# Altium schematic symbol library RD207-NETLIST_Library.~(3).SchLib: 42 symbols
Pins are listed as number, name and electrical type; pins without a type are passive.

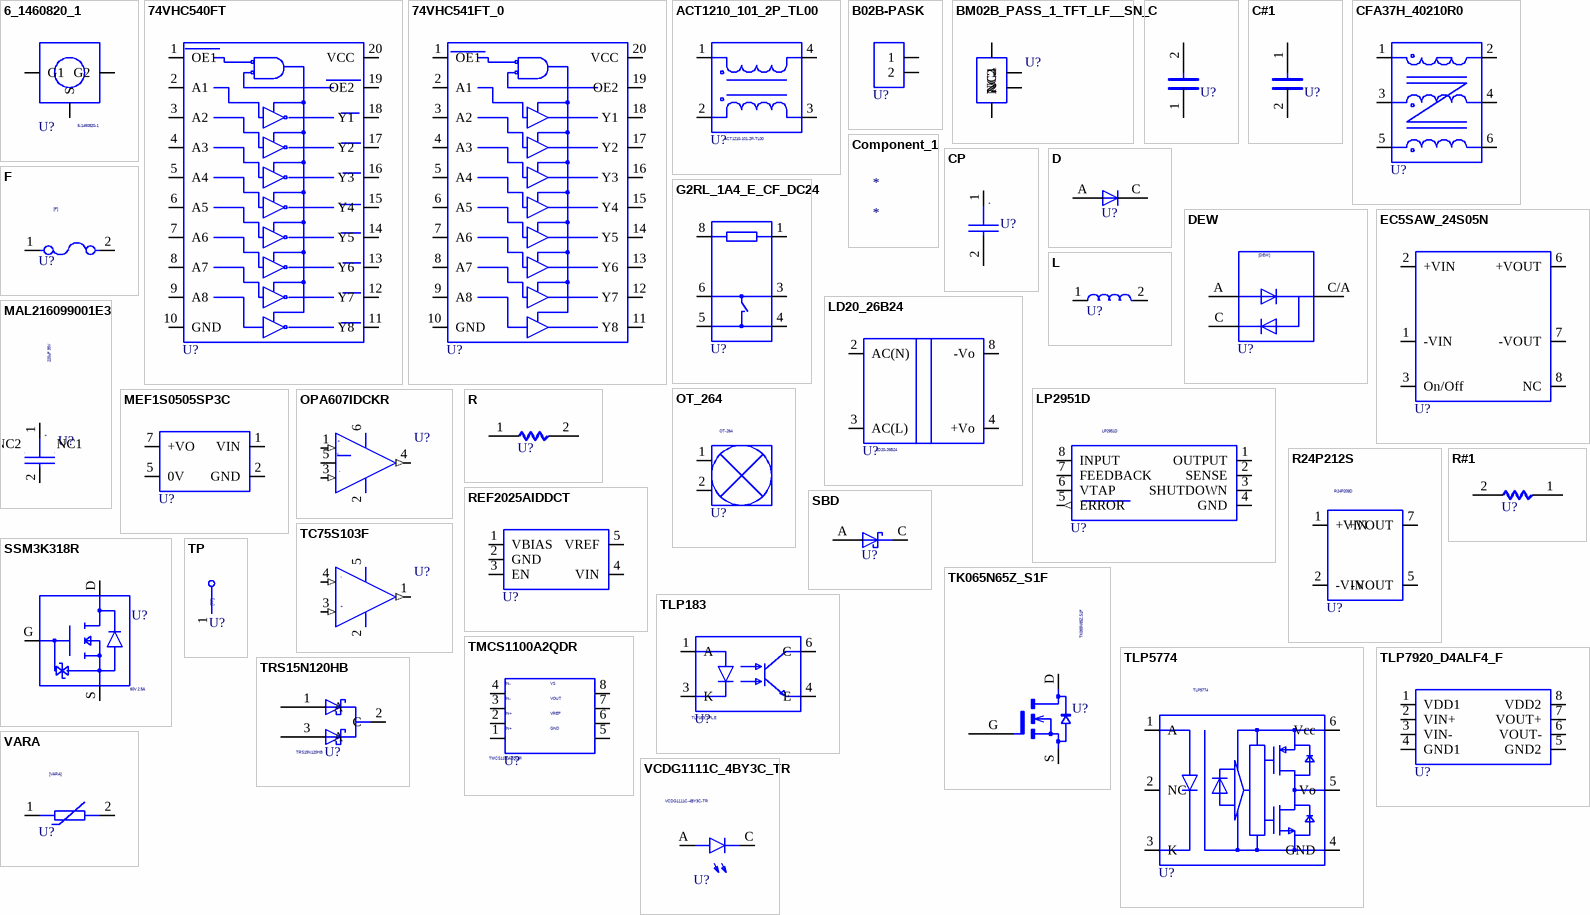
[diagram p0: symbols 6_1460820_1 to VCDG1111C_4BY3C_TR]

## 6_1460820_1
designator U?, comment 6-1460820-1
MMCX Connector, 170V; MANUFACTURER: TE Connectivity; TIME: 11:39:41; UPDATEUSER: t5459927; UPDATETIME: 13:55:13; SAVECOUNT: 2; SAVEAREA0: -9060,-19760,18940,737; OriginalSymbolOrigin: (0,0); Altium-Right: 40
pins: G1, G2, S

## 74VHC540FT
designator U?  (value not drawn)
Buffer; MANUFACTURER: TOSHIBA; TIME: 16:53:55; UPDATEUSER: t5459927; UPDATETIME: 14:02:13; SAVECOUNT: 3; SAVEAREA0: -17145,-25086,46711,10262; OriginalSymbolOrigin: (0,0); Altium-Right: 120; Altium-Bottom: 200
pins: 1 OE1, 2 A1, 3 A2, 4 A3, 5 A4, 6 A5, 7 A6, 8 A7, 9 A8, 10 GND, 11 Y8, 12 Y7, 13 Y6, 14 Y5, 15 Y4, 16 Y3, 17 Y2, 18 Y1, 19 OE2, 20 VCC

## 74VHC541FT_0
designator U?, comment 74VHC541FT  (value not drawn)
Buffer; MANUFACTURER: TOSHIBA; COMP: 74VHC541FT_0; TIME: 16:53:58; UPDATEUSER: t5459927; UPDATETIME: 13:53:55; SAVECOUNT: 7; SAVEAREA0: -71383,-60147,106563,38358; OriginalSymbolOrigin: (0,0); Altium-Right: 120; Altium-Bottom: 200
pins: 1 OE1, 2 A1, 3 A2, 4 A3, 5 A4, 6 A5, 7 A6, 8 A7, 9 A8, 10 GND, 11 Y8, 12 Y7, 13 Y6, 14 Y5, 15 Y4, 16 Y3, 17 Y2, 18 Y1, 19 OE2, 20 VCC

## ACT1210_101_2P_TL00
designator U?, comment ACT1210-101-2P-TL00
150mA; MAKER: TDK; NOTE: 100uH; TIME: 11:39:41; UPDATEUSER: t5459927; UPDATETIME: 16:14:20; SAVECOUNT: 2; SAVEAREA0: -3836,-15544,18561,852; OriginalSymbolOrigin: (0,0); Altium-Right: 60
pins: 1, 2, 3, 4

## B02B-PASK
designator U?, comment BM02B-PASS-1-TFT(LF)(SN)  (value not drawn)
Connector, 250V, 3A; MANUFACTURER: JST; COMP: B02B-PASK; NOTE: 2pin; TIME: 11:39:42; UPDATEUSER: t5459927; UPDATETIME: 16:50:18; SAVECOUNT: 6; SAVEAREA0: -5711,-10440,12954,3224; OriginalSymbolOrigin: (0,0); Altium-Right: 20; Altium-Bottom: 30
pins: 1, 2

## BM02B_PASS_1_TFT_LF__SN_
designator U?, comment BM02B-PASS-1-TFT(LF)(SN)  (value not drawn)
Connector, 250V, 3A; MANUFACTURER: JST; NOTE: 2pin; TIME: 11:39:42; UPDATEUSER: t5459927; UPDATETIME: 16:51:32; SAVECOUNT: 4; SAVEAREA0: -29189,-27933,36825,20394; OriginalSymbolOrigin: (0,0); Altium-Right: 20; Altium-Bottom: 30
pins: 1, 2, NC1, NC2

## C
designator U?  (value not drawn)
OriginalSymbolOrigin: (2540,7620); Altium-Right: 20; Altium-Bottom: 10
pins: 1, 2

## C#1
designator U?, comment C  (value not drawn)
OriginalSymbolOrigin: (2540,7620); Altium-Right: 20; Altium-Bottom: 10
pins: 1 2, 2 1

## CFA37H_40210R0
designator U?, comment CFA37H-40210R0  (value not drawn)
3phase Common Mode Choke; MAKER: Tamura; NOTE: 3phase, 4mH@100kHz, 10A; TIME: 11:39:42; UPDATEUSER: t5459927; UPDATETIME: 15:32:41; SAVECOUNT: 2; SAVEAREA0: -28588,-28970,43380,3822; OriginalSymbolOrigin: (0,0); Altium-Right: 60; Altium-Bottom: 80
pins: 1, 2, 3, 4, 5, 6

## Component_1
designator *

## CP
designator U?  (value not drawn)
SAVEAREA0: -1450,-153,20294,13055; SAVECOUNT: 52; TIME: 15:02:55; UPDATEUSER: fukuda-y; UPDATETIME: 16:13:42; OriginalSymbolOrigin: (2540,10160); Altium-Right: 20
pins: 1 2, 2 1

## D
designator U?  (value not drawn)
SAVEAREA0: -225,-91,12804,7836; SAVECOUNT: 3; TIME: 14:49:55; UPDATEUSER: 19870035; UPDATETIME: 14:20:16; OriginalSymbolOrigin: (5080,5080); Altium-Right: 10; Altium-Bottom: 20
pins: A, C

## DEW
designator U?  (value not drawn)
SAVEAREA0: -10024,-234,32508,20938; TIME: 14:49:55; UPDATEUSER: 19990028; UPDATETIME: 14:00:58; SAVECOUNT: 4; OriginalSymbolOrigin: (5080,17780); Altium-Right: 50; Altium-Bottom: 60
pins: A, C, C/A AC

## EC5SAW_24S05N
designator U?, comment EC5SAW-24S05N  (value not drawn)
DC/DC Converter; MANUFACTURER: CINCON; TIME: 11:39:40; UPDATEUSER: t5459927; UPDATETIME: 14:27:04; SAVECOUNT: 4; SAVEAREA0: -8840,-26929,31144,2341; OriginalSymbolOrigin: (0,0); Altium-Right: 90; Altium-Bottom: 100
pins: 1 -VIN, 2 +VIN, 3 On/Off, 6 +VOUT, 7 -VOUT, 8 NC

## F
designator U?  (value not drawn)
OriginalSymbolOrigin: (2540,5080); Altium-Right: 40; Altium-Bottom: 20
pins: 1, 2

## G2RL_1A4_E_CF_DC24
designator U?, comment G2RL-1A4-E-CF DC24  (value not drawn)
Power Relay; MANUFACTURER: OMRON; NOTE: 16A AC250V; TIME: 11:39:42; UPDATEUSER: t5459927; UPDATETIME: 16:09:17; SAVECOUNT: 4; SAVEAREA0: -30398,-23390,50563,13500; OriginalSymbolOrigin: (5080,7620); Altium-Right: 40; Altium-Bottom: 80
pins: 1, 3, 4, 5, 6, 8

## L
designator U?  (value not drawn)
OriginalSymbolOrigin: (2540,5080); Altium-Right: 30; Altium-Bottom: 20
pins: 1, 2

## LD20_26B24
designator U?, comment LD20-26B24
AC/DC Converter; MANUFACTURER: Mornsun; TIME: 11:39:42; UPDATEUSER: t5459927; UPDATETIME: 17:04:57; SAVECOUNT: 2; SAVEAREA0: -3533,-18371,23278,1256; OriginalSymbolOrigin: (0,0); Altium-Right: 80; Altium-Bottom: 70
pins: 2 AC(N), 3 AC(L), 4 +Vo, 8 -Vo

## LP2951D
designator U?
Voltage Regulators; MANUFACTURER: Txsas Instruments; TIME: 16:53:55; UPDATEUSER: t5459927; UPDATETIME: 16:15:29; SAVECOUNT: 3; SAVEAREA0: -15946,-25147,36340,13186; OriginalSymbolOrigin: (0,0); Altium-Right: 110; Altium-Bottom: 50
pins: 1 OUTPUT, 2 SENSE, 3 SHUTDOWN, 4 GND, 5 ERROR (out), 6 VTAP, 7 FEEDBACK, 8 INPUT

## MAL216099001E3
designator U?  NOTE: 220uF 35V  (hidden comment: MAL216099001E3)
Aluminum,35V,±20%; MANUFACTURER: Vishay; TIME: 11:39:41; UPDATEUSER: t5459927; UPDATETIME: 17:02:27; SAVECOUNT: 2; SAVEAREA0: -15593,-10586,20389,5809; OriginalSymbolOrigin: (0,0); Altium-Right: 20
pins: 1, 2, NC1, NC2

## MEF1S0505SP3C
designator U?  (value not drawn)
DC/DC Converter; MANUFACTURER: MORNSUN; TIME: 16:53:55; UPDATEUSER: t5459927; UPDATETIME: 13:45:31; SAVECOUNT: 4; SAVEAREA0: -2499,-12525,17820,2350; OriginalSymbolOrigin: (0,0); Altium-Right: 60; Altium-Bottom: 40
pins: 1 VIN, 2 GND, 5 0V, 7 +VO

## OPA607IDCKR
designator U?  (value not drawn)
TIME: 16:31:59; UPDATEUSER: t5459927; UPDATETIME: 14:13:01; SAVECOUNT: 17; SAVEAREA0: -9767,-7670,25158,17897; OriginalSymbolOrigin: (2540,10160); Altium-Right: 40
pins: 1 (in), 2 (in), 3 (in), 4 (out), 5 (io), 6 (in)

## OT_264
designator U?, comment OT-264
Terminal, 50A, M4; MANUFACTURER: Osada; TIME: 11:39:39; UPDATEUSER: t5459927; UPDATETIME: 13:18:21; SAVECOUNT: 2; SAVEAREA0: -3825,-10384,11105,546; OriginalSymbolOrigin: (0,0); Altium-Right: 40
pins: 1, 2

## R
designator U?  (value not drawn)
OriginalSymbolOrigin: (5080,5080); Altium-Right: 20
pins: 1, 2

## R24P212S
designator U?, comment R24P209D
DC/DC Converter; MANUFACTURER: RECOM; COMP: R24P212S; TIME: 16:53:55; UPDATEUSER: t5459927; UPDATETIME: 16:30:09; SAVECOUNT: 6; SAVEAREA0: -9940,-15240,22833,0; OriginalSymbolOrigin: (0,0); Altium-Right: 50; Altium-Bottom: 60
pins: 1 +VIN, 2 -VIN, 5 -VOUT, 7 +VOUT

## R#1
designator U?, comment R  (value not drawn)
OriginalSymbolOrigin: (5080,5080); Altium-Right: 20
pins: 1 2, 2 1

## REF2025AIDDCT
designator U?  (value not drawn)
Voltage References; MANUFACTURER: Texas Instruments; TIME: 11:39:41; UPDATEUSER: t5459927; UPDATETIME: 14:37:37; SAVECOUNT: 2; SAVEAREA0: -19574,-17685,36869,8033; OriginalSymbolOrigin: (0,0); Altium-Right: 70; Altium-Bottom: 40
pins: 1 VBIAS, 2 GND, 3 EN, 4 VIN, 5 VREF

## SBD
designator U?  (value not drawn)
SAVEAREA0: -4630,-153,17114,13055; TIME: 14:49:55; UPDATEUSER: fukuda-y; UPDATETIME: 08:16:22; SAVECOUNT: 9; OriginalSymbolOrigin: (5080,5080); Altium-Right: 20
pins: A, C

## SSM3K318R
designator U?  NOTE: 60V 2.5A  (hidden comment: SSM3K318R)
MOSFET; MANUFACTURER: TOSHIBA; TIME: 11:39:41; UPDATEUSER: t5459927; UPDATETIME: 14:45:44; SAVECOUNT: 2; SAVEAREA0: -8920,-18190,20944,3672; OriginalSymbolOrigin: (0,0); Altium-Right: 60
pins: D, G, S

## TC75S103F
designator U?  (value not drawn)
COMP: OPA4325IPWR_4; TIME: 16:31:59; UPDATEUSER: t5459927; UPDATETIME: 13:42:20; SAVECOUNT: 13; SAVEAREA0: 0,-513,15240,10643; OriginalSymbolOrigin: (2540,10160); Altium-Right: 40
pins: 1 (out), 2 (in), 3 (in), 4 (in), 5 (in)

## TK065N65Z_S1F
designator U?, comment TK065N65Z,S1F
Power MOS FET; MANUFACTURER: TOSHIBA; NOTE: 650V 30A; TIME: 11:39:42; UPDATEUSER: t5459927; UPDATETIME: 13:16:21; SAVECOUNT: 2; SAVEAREA0: -16850,-13021,18411,3375; OriginalSymbolOrigin: (0,0); Altium-Right: 40
pins: D, G, S

## TLP183
designator U?, comment TLP183(TPL,E
Photocoupler; MANUFACTURER: TOSHIBA; TIME: 11:39:41; UPDATEUSER: t5459927; UPDATETIME: 14:44:44; SAVECOUNT: 2; SAVEAREA0: -18362,-25993,35930,13752; OriginalSymbolOrigin: (0,0); Altium-Right: 70; Altium-Bottom: 50
pins: 1 A, 3 K, 4 E, 6 C

## TLP5774
designator U?
Photocouplers; MAKER: TOSHIBA; NOTE: 5kV 8mm; TIME: 11:39:41; UPDATEUSER: t5459927; UPDATETIME: 14:14:00; SAVECOUNT: 2; SAVEAREA0: -5083,-25908,32249,1421; OriginalSymbolOrigin: (0,0); Altium-Right: 110; Altium-Bottom: 100
pins: 1 A, 2 NC, 3 K, 4 GND, 5 Vo, 6 Vcc

## TLP7920_D4ALF4_F
designator U?, comment TLP7920(D4ALF1,F  (value not drawn)
Photocoupler; MANUFACTURER: TOSHIBA; COMP: TLP7920(D4ALF1,F_0; TIME: 16:53:58; UPDATEUSER: t5459927; UPDATETIME: 15:20:44; SAVECOUNT: 3; SAVEAREA0: -6054,-17255,23482,4367; OriginalSymbolOrigin: (0,0); Altium-Right: 90; Altium-Bottom: 50
pins: 1 VDD1, 2 VIN+, 3 VIN-, 4 GND1, 5 GND2, 6 VOUT-, 7 VOUT+, 8 VDD2

## TMCS1100A2QDR
designator U?
TIME: 11:39:42; UPDATEUSER: t5459927; UPDATETIME: 14:02:58; SAVECOUNT: 5; SAVEAREA0: -9737,-18768,24721,6457; OriginalSymbolOrigin: (0,0); Altium-Right: 60; Altium-Bottom: 50
pins: 1, 2, 3, 4, 5, 6, 7, 8

## TP
designator U?  (value not drawn)
TIME: 16:12:21; UPDATEUSER: fukuda-y; UPDATETIME: 16:18:11; SAVECOUNT: 2; SAVEAREA0: -242,-92,12810,7836; OriginalSymbolOrigin: (0,7620); Altium-Right: 20; Altium-Bottom: 30
pins: 1

## TRS15N120HB
designator U?
SiC Schottky Barrier Diode Array; MANUFACTURER: TOSHIBA; NOTE: 1200V; TIME: 11:39:42; UPDATEUSER: t5459927; SAVECOUNT: 1; OriginalSymbolOrigin: (0,0); Altium-Right: 30; Altium-Bottom: 40
pins: 1 A, 2 C, 3 A

## VARA
designator U?  (value not drawn)
SAVEAREA0: -9950,-8554,25168,13619; SAVECOUNT: 12; TIME: 09:56:50; UPDATEUSER: tomizawa-y; OriginalSymbolOrigin: (2540,5080); Altium-Right: 40; Altium-Bottom: 20
pins: 1, 2

## VCDG1111C_4BY3C_TR
designator U?, comment VCDG1111C-4BY3C-TR
LED; MANUFACTURER: STANLEY; NOTE: Green; TIME: 16:53:54; UPDATEUSER: t5459927; SAVECOUNT: 1; OriginalSymbolOrigin: (0,-2540); Altium-Right: 30
pins: A, C

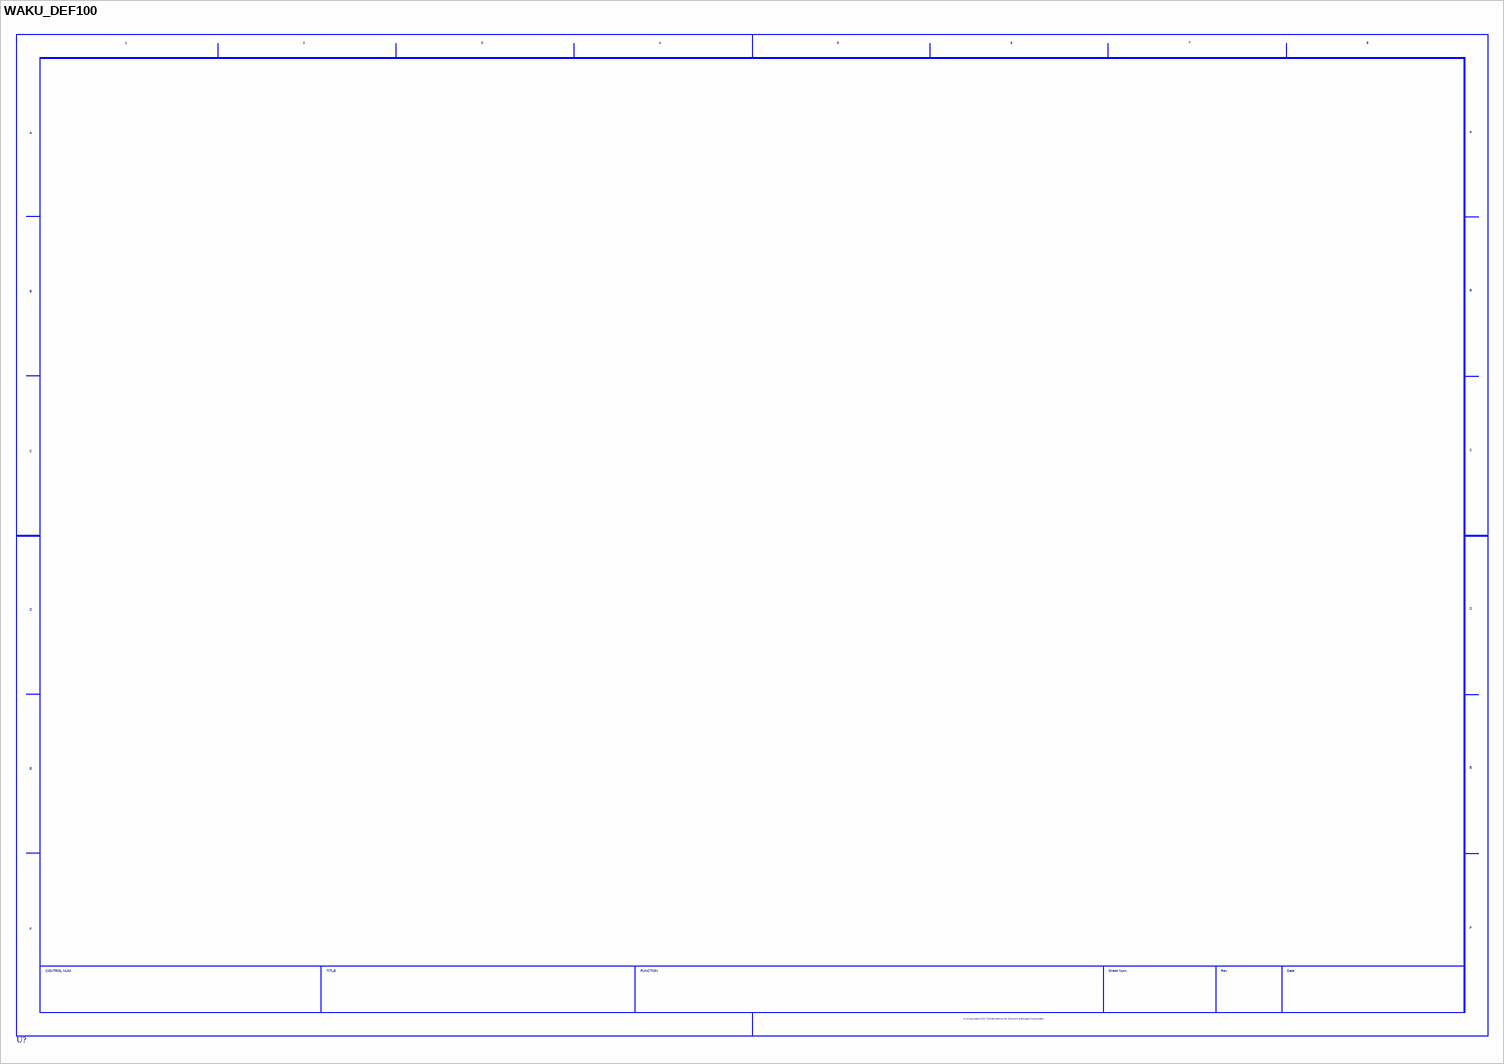
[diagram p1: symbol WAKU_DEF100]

## WAKU_DEF100
designator U?  (value not drawn)
PLOTTIME: HH:MM; SAVEAREA0: 22200,72372,612276,319236; TIME: 14:30:25; UPDATEUSER: t5459927; UPDATETIME: 17:12:32; SAVECOUNT: 7; OriginalSymbolOrigin: (10160,284480); Altium-Right: 1570; Altium-Bottom: 1070

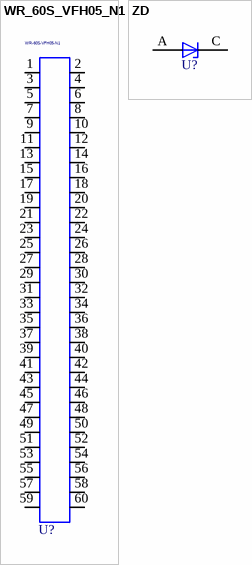
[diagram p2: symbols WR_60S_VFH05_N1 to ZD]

## WR_60S_VFH05_N1
designator U?, comment WR-60S-VFH05-N1
Terminal, 200V, 0.3A; MANUFACTURER: JAE; NOTE: 60pin; TIME: 16:53:54; UPDATEUSER: t5459927; UPDATETIME: 14:46:38; SAVECOUNT: 2; SAVEAREA0: -56595,-80318,58967,4405; OriginalSymbolOrigin: (0,0); Altium-Right: 20; Altium-Bottom: 310
pins: 1, 2, 3, 4, 5, 6, 7, 8, 9, 10, 11, 12, 13, 14, 15, 16, 17, 18, 19, 20, 21, 22, 23, 24, 25, 26, 27, 28, 29, 30, 31, 32, 33, 34, 35, 36, 37, 38, 39, 40, 41, 42, 43, 44, 45, 46, 47, 48, 49, 50, 51, 52, 53, 54, 55, 56, 57, 58, 59, 60

## ZD
designator U?  (value not drawn)
SAVEAREA0: -4630,-153,17114,13055; TIME: 14:49:55; UPDATEUSER: fukuda-y; UPDATETIME: 08:18:42; SAVECOUNT: 6; OriginalSymbolOrigin: (5080,5080); Altium-Right: 10; Altium-Bottom: 20
pins: A, C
